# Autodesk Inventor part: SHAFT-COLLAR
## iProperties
Created: 2007-08
Part Number: SHAFT-COLLAR
Material: Stainless Steel
Document SubType Name: Modeling
Density: 8.08 g/cm^3
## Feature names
1. Base1
